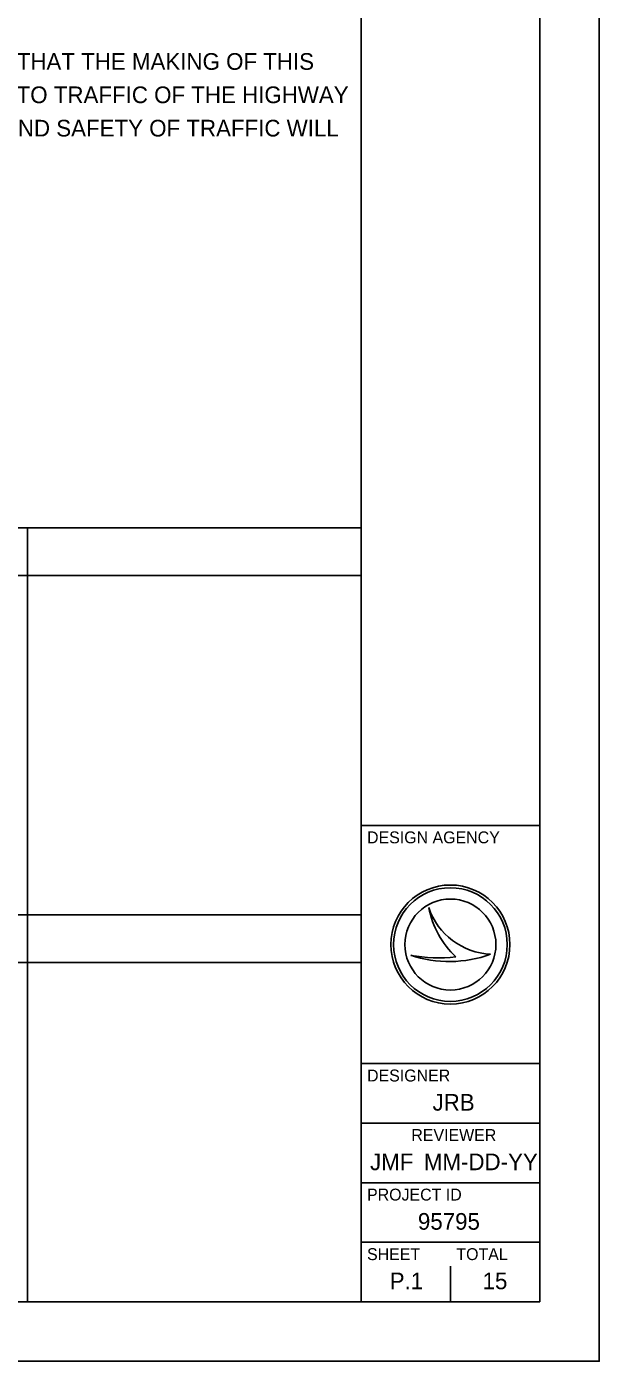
# Model space of a CAD drawing. Extents: x 0 to 34, y 0 to 22.
# Drawn here: x 29.19 to 34, y 0 to 11.21 of the extents above; entities that cross this region are included whole.
import ezdxf

# ---------------------------------------------------------------- set-up
doc = ezdxf.new("R2010")
doc.units = 0
for name, color, linetype in [('SH_Border', 7, 'Continuous'), ('SH_Cut_Line', 7, 'Continuous'), ('SH_Data', 7, 'Continuous'), ('SH_Text', 7, 'Continuous')]:
    doc.layers.add(name, color=color, linetype=linetype)

msp = doc.modelspace()

# ---------------------------------------------------------------- linework, layer by layer
at = {"layer": 'SH_Border'}
for p, q in [((32, 0.5), (32, 21.5)), ((32, 4.5), (33.5, 4.5)), ((32, 2.5), (33.5, 2.5)), ((32, 2), (33.5, 2)), ((32, 1.5), (33.5, 1.5)), ((32, 1), (33.5, 1))]:
    msp.add_line(p, q, dxfattribs=at)
msp.add_lwpolyline([(1.5, 21.5), (33.5, 21.5), (33.5, 0.5), (1.5, 0.5)], close=True, dxfattribs=at)
at = {"layer": 'SH_Cut_Line'}
msp.add_lwpolyline([(0, 0), (34, 0), (34, 22), (0, 22)], close=True, dxfattribs=at)
at = {"layer": 'SH_Data'}
for p, q in [((26.4, 6.6), (29.2, 6.6)), ((29.2, 6.6), (32, 6.6)), ((32.567, 3.81), (32.567, 3.81)), ((32.75, 3.5), (32.75, 3.5)), ((32.417, 3.41), (32.417, 3.41)), ((33.087, 3.419), (33.087, 3.419)), ((26.4, 3.35), (29.2, 3.35)), ((29.2, 3.35), (32, 3.35)), ((32.75, 0.5), (32.75, 0.8)), ((32.375, 0.675), (32.375, 0.675))]:
    msp.add_line(p, q, dxfattribs=at)
for points in [[(29.2, 7), (26.4, 7), (26.4, 3.75), (29.2, 3.75)], [(32, 7), (29.2, 7), (29.2, 3.75), (32, 3.75)], [(29.2, 3.75), (26.4, 3.75), (26.4, 0.5), (29.2, 0.5)], [(32, 3.75), (29.2, 3.75), (29.2, 0.5), (32, 0.5)]]:
    msp.add_lwpolyline(points, close=True, dxfattribs=at)
for radius in [0.5, 0.477, 0.477, 0.382]:
    msp.add_circle((32.75, 3.5), radius, dxfattribs=at)
for centre, radius, start, end in [((33.116, 3.998), 0.58, 198.9257, 198.9319), ((33.347, 3.97), 0.796, 191.6379, 191.6421), ((33.116, 3.998), 0.58, 198.9319, 267.1657), ((33.347, 3.97), 0.796, 191.6421, 226.0947), ((32.739, 4.37), 1.013, 251.4576, 290.0832), ((32.648, 4.654), 1.266, 259.4964, 259.4995), ((32.739, 4.37), 1.013, 251.4527, 251.4576), ((32.648, 4.654), 1.266, 259.4995, 276.6672)]:
    msp.add_arc(centre, radius, start, end, dxfattribs=at)

# ---------------------------------------------------------------- texts
for s, height, p in [('DESIGN AGENCY', 0.1, (32.05, 4.35)), ('DESIGNER', 0.1, (32.05, 2.35)), ('JRB', 0.14, (32.6, 2.105)), ('REVIEWER', 0.1, (32.422, 1.85)), ('JMF', 0.14, (32.075, 1.605)), ('MM-DD-YY', 0.14, (32.527, 1.605)), ('PROJECT ID', 0.1, (32.05, 1.35)), ('95795', 0.14, (32.477, 1.105)), ('SHEET', 0.1, (32.05, 0.85)), ('TOTAL', 0.1, (32.8, 0.85)), ('P.1', 0.14, (32.24, 0.605)), ('15', 0.14, (33.02, 0.605))]:
    msp.add_text(s, height=height, dxfattribs=at).set_placement(p)
at = {"layer": 'SH_Text'}
for s, p in [('I HEREBY APPROVE THESE PLANS AND DECLARE THAT THE MAKING OF THIS', (24.5, 10.846)), ('IMPROVEMENT WILL NOT REQUIRE THE CLOSING TO TRAFFIC OF THE HIGHWAY', (24.5, 10.566)), ('AND THAT PROVISIONS FOR THE MAINTENANCE AND SAFETY OF TRAFFIC WILL', (24.5, 10.286))]:
    msp.add_text(s, height=0.14, dxfattribs=at).set_placement(p)

doc.saveas('drawing.dxf')
